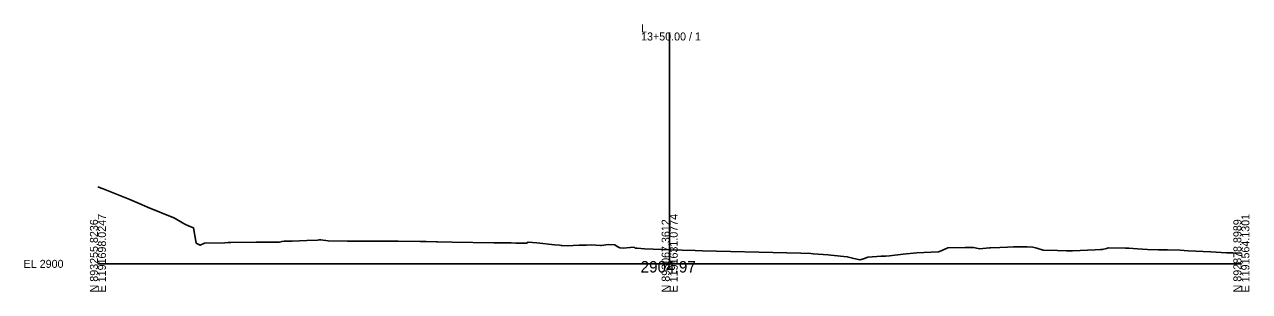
# Model space of a CAD drawing. Extents: x 1791751 to 1799722, y 648637 to 665635.
# Drawn here: x 1792163.2 to 1792591.7, y 656030.3 to 656123.9 of the extents above; entities that cross this region are included whole.
import ezdxf

# ---------------------------------------------------------------- set-up
doc = ezdxf.new("R2010")
doc.units = 0
for name, color, linetype in [('Exist Cross Section Cell', 7, 'Continuous'), ('Exist XS Center Line Elevation Label', 7, 'Continuous'), ('Exist XS Ground Line', 7, 'Continuous')]:
    doc.layers.add(name, color=color, linetype=linetype)

msp = doc.modelspace()

# ---------------------------------------------------------------- linework, layer by layer
at = {"layer": 'Exist Cross Section Cell'}
for p, q in [((1792388.88, 656040.04), (1792388.88, 656121.06)), ((1792388.88, 656040.04), (1792388.88, 656121.06)), ((1792388.88, 656040.04), (1792388.88, 656121.06)), ((1792188.88, 656040.04), (1792388.88, 656040.04)), ((1792188.88, 656040.04), (1792388.88, 656040.04)), ((1792188.88, 656040.04), (1792388.88, 656040.04)), ((1792388.88, 656040.04), (1792588.88, 656040.04)), ((1792388.88, 656040.04), (1792588.88, 656040.04)), ((1792388.88, 656040.04), (1792588.88, 656040.04))]:
    msp.add_line(p, q, dxfattribs=at)
at = {"layer": 'Exist XS Ground Line'}
msp.add_lwpolyline([(1792188.88, 656067.04), (1792190.34, 656066.46), (1792190.68, 656066.32), (1792200.03, 656062.58), (1792203.33, 656061.15), (1792204.12, 656060.81), (1792206.2, 656059.89), (1792215.41, 656056.14), (1792215.94, 656055.86), (1792218.48, 656054.42), (1792219.26, 656053.91), (1792220.83, 656053.24), (1792222.35, 656052.64), (1792223.27, 656047.32), (1792224.66, 656046.56), (1792226.12, 656047.31), (1792233.32, 656047.45), (1792234.41, 656047.47), (1792235.41, 656047.47), (1792244.2, 656047.65), (1792246.19, 656047.61), (1792248.65, 656047.68), (1792250.78, 656047.67), (1792252.35, 656047.67), (1792253.32, 656047.87), (1792254.01, 656047.94), (1792256.77, 656048.01), (1792261.95, 656048.25), (1792265.63, 656048.38), (1792266.25, 656048.39), (1792266.85, 656048.5), (1792269.43, 656048.15), (1792276.18, 656048.02), (1792279.82, 656047.94), (1792281.43, 656048), (1792281.93, 656047.99), (1792291.31, 656047.94), (1792293.88, 656047.93), (1792301.57, 656047.89), (1792302.86, 656047.89), (1792303.25, 656047.88), (1792303.65, 656047.88), (1792307.28, 656047.8), (1792307.67, 656047.79), (1792312.81, 656047.67), (1792327.42, 656047.44), (1792330.53, 656047.4), (1792333.48, 656047.35), (1792335.06, 656047.32), (1792338.82, 656047.26), (1792339.39, 656047.67), (1792342.38, 656047.35), (1792348.58, 656046.69), (1792350.31, 656046.52), (1792350.88, 656046.47), (1792351.19, 656046.44), (1792352.99, 656046.3), (1792357.22, 656046.58), (1792357.64, 656046.53), (1792359.83, 656046.6), (1792361.41, 656046.66), (1792364.7, 656046.47), (1792365.02, 656046.43), (1792367.41, 656046.78), (1792369.69, 656046.72), (1792370.54, 656046.06), (1792371.49, 656045.64), (1792372.57, 656045.57), (1792375.1, 656045.77), (1792376.42, 656045.83), (1792376.87, 656045.55), (1792377.56, 656045.51), (1792380.02, 656045.35), (1792383.16, 656045.22), (1792388.88, 656045), (1792389.22, 656044.99), (1792393.23, 656044.86), (1792397.79, 656044.69), (1792400.4, 656044.65), (1792429.91, 656043.86), (1792434.71, 656043.73), (1792438.27, 656043.64), (1792439.05, 656043.57), (1792444.35, 656043.19), (1792445.31, 656043.1), (1792451.02, 656042.52), (1792452.81, 656041.97), (1792455.46, 656041.49), (1792456.69, 656041.8), (1792458.22, 656042.41), (1792462.9, 656042.68), (1792464.33, 656042.75), (1792465.74, 656042.83), (1792470.6, 656043.47), (1792475.32, 656043.86), (1792477.76, 656043.97), (1792482.98, 656044.19), (1792483.91, 656044.6), (1792486.14, 656045.68), (1792492.25, 656045.71), (1792495.21, 656045.72), (1792496.85, 656045.41), (1792497.22, 656045.33), (1792500.82, 656045.62), (1792501.14, 656045.64), (1792504.37, 656045.76), (1792507.04, 656045.87), (1792509.2, 656045.96), (1792513.96, 656045.97), (1792515.9, 656045.93), (1792517.35, 656045.55), (1792519.49, 656044.83), (1792524.56, 656044.69), (1792527.75, 656044.6), (1792528.56, 656044.6), (1792529.81, 656044.61), (1792537.71, 656044.95), (1792539.6, 656045.02), (1792540.22, 656045.05), (1792541.75, 656045.37), (1792542.44, 656045.63), (1792548.32, 656045.54), (1792548.69, 656045.53), (1792549.46, 656045.49), (1792552.49, 656045.29), (1792555.99, 656045.01), (1792559.85, 656044.89), (1792563.05, 656044.89), (1792567.41, 656044.78), (1792570.32, 656044.62), (1792578.24, 656044.21), (1792583.62, 656043.95), (1792585.84, 656043.88), (1792588.88, 656043.78)], dxfattribs=at)
msp.add_lwpolyline([(1792188.88, 656067.04), (1792190.34, 656066.46), (1792190.68, 656066.32), (1792200.03, 656062.58), (1792203.33, 656061.15), (1792204.12, 656060.81), (1792206.2, 656059.89), (1792215.41, 656056.14), (1792215.94, 656055.86), (1792218.48, 656054.42), (1792219.26, 656053.91), (1792220.83, 656053.24), (1792222.35, 656052.64), (1792223.27, 656047.32), (1792224.66, 656046.56), (1792226.12, 656047.31), (1792233.32, 656047.45), (1792234.41, 656047.47), (1792235.41, 656047.47), (1792244.2, 656047.65), (1792246.19, 656047.61), (1792248.65, 656047.68), (1792250.78, 656047.67), (1792252.35, 656047.67), (1792253.32, 656047.87), (1792254.01, 656047.94), (1792256.77, 656048.01), (1792261.95, 656048.25), (1792265.63, 656048.38), (1792266.25, 656048.39), (1792266.85, 656048.5), (1792269.43, 656048.15), (1792276.18, 656048.02), (1792279.82, 656047.94), (1792281.43, 656048), (1792281.93, 656047.99), (1792291.31, 656047.94), (1792293.88, 656047.93), (1792301.57, 656047.89), (1792302.86, 656047.89), (1792303.25, 656047.88), (1792303.65, 656047.88), (1792307.28, 656047.8), (1792307.67, 656047.79), (1792312.81, 656047.67), (1792327.42, 656047.44), (1792330.53, 656047.4), (1792333.48, 656047.35), (1792335.06, 656047.32), (1792338.82, 656047.26), (1792339.39, 656047.67), (1792342.38, 656047.35), (1792348.58, 656046.69), (1792350.31, 656046.52), (1792350.88, 656046.47), (1792351.19, 656046.44), (1792352.99, 656046.3), (1792357.22, 656046.58), (1792357.64, 656046.53), (1792359.83, 656046.6), (1792361.41, 656046.66), (1792364.7, 656046.47), (1792365.02, 656046.43), (1792367.41, 656046.78), (1792369.69, 656046.72), (1792370.54, 656046.06), (1792371.49, 656045.64), (1792372.57, 656045.57), (1792375.1, 656045.77), (1792376.42, 656045.83), (1792376.87, 656045.55), (1792377.56, 656045.51), (1792380.02, 656045.35), (1792383.16, 656045.22), (1792388.88, 656045), (1792389.22, 656044.99), (1792393.23, 656044.86), (1792397.79, 656044.69), (1792400.4, 656044.65), (1792429.91, 656043.86), (1792434.71, 656043.73), (1792438.27, 656043.64), (1792439.05, 656043.57), (1792444.35, 656043.19), (1792445.31, 656043.1), (1792451.02, 656042.52), (1792452.81, 656041.97), (1792455.46, 656041.49), (1792456.69, 656041.8), (1792458.22, 656042.41), (1792462.9, 656042.68), (1792464.33, 656042.75), (1792465.74, 656042.83), (1792470.6, 656043.47), (1792475.32, 656043.86), (1792477.76, 656043.97), (1792482.98, 656044.19), (1792483.91, 656044.6), (1792486.14, 656045.68), (1792492.25, 656045.71), (1792495.21, 656045.72), (1792496.85, 656045.41), (1792497.22, 656045.33), (1792500.82, 656045.62), (1792501.14, 656045.64), (1792504.37, 656045.76), (1792507.04, 656045.87), (1792509.2, 656045.96), (1792513.96, 656045.97), (1792515.9, 656045.93), (1792517.35, 656045.55), (1792519.49, 656044.83), (1792524.56, 656044.69), (1792527.75, 656044.6), (1792528.56, 656044.6), (1792529.81, 656044.61), (1792537.71, 656044.95), (1792539.6, 656045.02), (1792540.22, 656045.05), (1792541.75, 656045.37), (1792542.44, 656045.63), (1792548.32, 656045.54), (1792548.69, 656045.53), (1792549.46, 656045.49), (1792552.49, 656045.29), (1792555.99, 656045.01), (1792559.85, 656044.89), (1792563.05, 656044.89), (1792567.41, 656044.78), (1792570.32, 656044.62), (1792578.24, 656044.21), (1792583.62, 656043.95), (1792585.84, 656043.88), (1792588.88, 656043.78)], dxfattribs=at)
msp.add_lwpolyline([(1792188.88, 656067.04), (1792190.34, 656066.46), (1792190.68, 656066.32), (1792200.03, 656062.58), (1792203.33, 656061.15), (1792204.12, 656060.81), (1792206.2, 656059.89), (1792215.41, 656056.14), (1792215.94, 656055.86), (1792218.48, 656054.42), (1792219.26, 656053.91), (1792220.83, 656053.24), (1792222.35, 656052.64), (1792223.27, 656047.32), (1792224.66, 656046.56), (1792226.12, 656047.31), (1792233.32, 656047.45), (1792234.41, 656047.47), (1792235.41, 656047.47), (1792244.2, 656047.65), (1792246.19, 656047.61), (1792248.65, 656047.68), (1792250.78, 656047.67), (1792252.35, 656047.67), (1792253.32, 656047.87), (1792254.01, 656047.94), (1792256.77, 656048.01), (1792261.95, 656048.25), (1792265.63, 656048.38), (1792266.25, 656048.39), (1792266.85, 656048.5), (1792269.43, 656048.15), (1792276.18, 656048.02), (1792279.82, 656047.94), (1792281.43, 656048), (1792281.93, 656047.99), (1792291.31, 656047.94), (1792293.88, 656047.93), (1792301.57, 656047.89), (1792302.86, 656047.89), (1792303.25, 656047.88), (1792303.65, 656047.88), (1792307.28, 656047.8), (1792307.67, 656047.79), (1792312.81, 656047.67), (1792327.42, 656047.44), (1792330.53, 656047.4), (1792333.48, 656047.35), (1792335.06, 656047.32), (1792338.82, 656047.26), (1792339.39, 656047.67), (1792342.38, 656047.35), (1792348.58, 656046.69), (1792350.31, 656046.52), (1792350.88, 656046.47), (1792351.19, 656046.44), (1792352.99, 656046.3), (1792357.22, 656046.58), (1792357.64, 656046.53), (1792359.83, 656046.6), (1792361.41, 656046.66), (1792364.7, 656046.47), (1792365.02, 656046.43), (1792367.41, 656046.78), (1792369.69, 656046.72), (1792370.54, 656046.06), (1792371.49, 656045.64), (1792372.57, 656045.57), (1792375.1, 656045.77), (1792376.42, 656045.83), (1792376.87, 656045.55), (1792377.56, 656045.51), (1792380.02, 656045.35), (1792383.16, 656045.22), (1792388.88, 656045), (1792389.22, 656044.99), (1792393.23, 656044.86), (1792397.79, 656044.69), (1792400.4, 656044.65), (1792429.91, 656043.86), (1792434.71, 656043.73), (1792438.27, 656043.64), (1792439.05, 656043.57), (1792444.35, 656043.19), (1792445.31, 656043.1), (1792451.02, 656042.52), (1792452.81, 656041.97), (1792455.46, 656041.49), (1792456.69, 656041.8), (1792458.22, 656042.41), (1792462.9, 656042.68), (1792464.33, 656042.75), (1792465.74, 656042.83), (1792470.6, 656043.47), (1792475.32, 656043.86), (1792477.76, 656043.97), (1792482.98, 656044.19), (1792483.91, 656044.6), (1792486.14, 656045.68), (1792492.25, 656045.71), (1792495.21, 656045.72), (1792496.85, 656045.41), (1792497.22, 656045.33), (1792500.82, 656045.62), (1792501.14, 656045.64), (1792504.37, 656045.76), (1792507.04, 656045.87), (1792509.2, 656045.96), (1792513.96, 656045.97), (1792515.9, 656045.93), (1792517.35, 656045.55), (1792519.49, 656044.83), (1792524.56, 656044.69), (1792527.75, 656044.6), (1792528.56, 656044.6), (1792529.81, 656044.61), (1792537.71, 656044.95), (1792539.6, 656045.02), (1792540.22, 656045.05), (1792541.75, 656045.37), (1792542.44, 656045.63), (1792548.32, 656045.54), (1792548.69, 656045.53), (1792549.46, 656045.49), (1792552.49, 656045.29), (1792555.99, 656045.01), (1792559.85, 656044.89), (1792563.05, 656044.89), (1792567.41, 656044.78), (1792570.32, 656044.62), (1792578.24, 656044.21), (1792583.62, 656043.95), (1792585.84, 656043.88), (1792588.88, 656043.78)], dxfattribs=at)
msp.add_lwpolyline([(1792188.88, 656067.04), (1792190.34, 656066.46), (1792190.68, 656066.32), (1792200.03, 656062.58), (1792203.33, 656061.15), (1792204.12, 656060.81), (1792206.2, 656059.89), (1792215.41, 656056.14), (1792215.94, 656055.86), (1792218.48, 656054.42), (1792219.26, 656053.91), (1792220.83, 656053.24), (1792222.35, 656052.64), (1792223.27, 656047.32), (1792224.66, 656046.56), (1792226.12, 656047.31), (1792233.32, 656047.45), (1792234.41, 656047.47), (1792235.41, 656047.47), (1792244.2, 656047.65), (1792246.19, 656047.61), (1792248.65, 656047.68), (1792250.78, 656047.67), (1792252.35, 656047.67), (1792253.32, 656047.87), (1792254.01, 656047.94), (1792256.77, 656048.01), (1792261.95, 656048.25), (1792265.63, 656048.38), (1792266.25, 656048.39), (1792266.85, 656048.5), (1792269.43, 656048.15), (1792276.18, 656048.02), (1792279.82, 656047.94), (1792281.43, 656048), (1792281.93, 656047.99), (1792291.31, 656047.94), (1792293.88, 656047.93), (1792301.57, 656047.89), (1792302.86, 656047.89), (1792303.25, 656047.88), (1792303.65, 656047.88), (1792307.28, 656047.8), (1792307.67, 656047.79), (1792312.81, 656047.67), (1792327.42, 656047.44), (1792330.53, 656047.4), (1792333.48, 656047.35), (1792335.06, 656047.32), (1792338.82, 656047.26), (1792339.39, 656047.67), (1792342.38, 656047.35), (1792348.58, 656046.69), (1792350.31, 656046.52), (1792350.88, 656046.47), (1792351.19, 656046.44), (1792352.99, 656046.3), (1792357.22, 656046.58), (1792357.64, 656046.53), (1792359.83, 656046.6), (1792361.41, 656046.66), (1792364.7, 656046.47), (1792365.02, 656046.43), (1792367.41, 656046.78), (1792369.69, 656046.72), (1792370.54, 656046.06), (1792371.49, 656045.64), (1792372.57, 656045.57), (1792375.1, 656045.77), (1792376.42, 656045.83), (1792376.87, 656045.55), (1792377.56, 656045.51), (1792380.02, 656045.35), (1792383.16, 656045.22), (1792388.88, 656045), (1792389.22, 656044.99), (1792393.23, 656044.86), (1792397.79, 656044.69), (1792400.4, 656044.65), (1792429.91, 656043.86), (1792434.71, 656043.73), (1792438.27, 656043.64), (1792439.05, 656043.57), (1792444.35, 656043.19), (1792445.31, 656043.1), (1792451.02, 656042.52), (1792452.81, 656041.97), (1792455.46, 656041.49), (1792456.69, 656041.8), (1792458.22, 656042.41), (1792462.9, 656042.68), (1792464.33, 656042.75), (1792465.74, 656042.83), (1792470.6, 656043.47), (1792475.32, 656043.86), (1792477.76, 656043.97), (1792482.98, 656044.19), (1792483.91, 656044.6), (1792486.14, 656045.68), (1792492.25, 656045.71), (1792495.21, 656045.72), (1792496.85, 656045.41), (1792497.22, 656045.33), (1792500.82, 656045.62), (1792501.14, 656045.64), (1792504.37, 656045.76), (1792507.04, 656045.87), (1792509.2, 656045.96), (1792513.96, 656045.97), (1792515.9, 656045.93), (1792517.35, 656045.55), (1792519.49, 656044.83), (1792524.56, 656044.69), (1792527.75, 656044.6), (1792528.56, 656044.6), (1792529.81, 656044.61), (1792537.71, 656044.95), (1792539.6, 656045.02), (1792540.22, 656045.05), (1792541.75, 656045.37), (1792542.44, 656045.63), (1792548.32, 656045.54), (1792548.69, 656045.53), (1792549.46, 656045.49), (1792552.49, 656045.29), (1792555.99, 656045.01), (1792559.85, 656044.89), (1792563.05, 656044.89), (1792567.41, 656044.78), (1792570.32, 656044.62), (1792578.24, 656044.21), (1792583.62, 656043.95), (1792585.84, 656043.88), (1792588.88, 656043.78)], dxfattribs=at)
msp.add_lwpolyline([(1792188.88, 656067.04), (1792190.34, 656066.46), (1792190.68, 656066.32), (1792200.03, 656062.58), (1792203.33, 656061.15), (1792204.12, 656060.81), (1792206.2, 656059.89), (1792215.41, 656056.14), (1792215.94, 656055.86), (1792218.48, 656054.42), (1792219.26, 656053.91), (1792220.83, 656053.24), (1792222.35, 656052.64), (1792223.27, 656047.32), (1792224.66, 656046.56), (1792226.12, 656047.31), (1792233.32, 656047.45), (1792234.41, 656047.47), (1792235.41, 656047.47), (1792244.2, 656047.65), (1792246.19, 656047.61), (1792248.65, 656047.68), (1792250.78, 656047.67), (1792252.35, 656047.67), (1792253.32, 656047.87), (1792254.01, 656047.94), (1792256.77, 656048.01), (1792261.95, 656048.25), (1792265.63, 656048.38), (1792266.25, 656048.39), (1792266.85, 656048.5), (1792269.43, 656048.15), (1792276.18, 656048.02), (1792279.82, 656047.94), (1792281.43, 656048), (1792281.93, 656047.99), (1792291.31, 656047.94), (1792293.88, 656047.93), (1792301.57, 656047.89), (1792302.86, 656047.89), (1792303.25, 656047.88), (1792303.65, 656047.88), (1792307.28, 656047.8), (1792307.67, 656047.79), (1792312.81, 656047.67), (1792327.42, 656047.44), (1792330.53, 656047.4), (1792333.48, 656047.35), (1792335.06, 656047.32), (1792338.82, 656047.26), (1792339.39, 656047.67), (1792342.38, 656047.35), (1792348.58, 656046.69), (1792350.31, 656046.52), (1792350.88, 656046.47), (1792351.19, 656046.44), (1792352.99, 656046.3), (1792357.22, 656046.58), (1792357.64, 656046.53), (1792359.83, 656046.6), (1792361.41, 656046.66), (1792364.7, 656046.47), (1792365.02, 656046.43), (1792367.41, 656046.78), (1792369.69, 656046.72), (1792370.54, 656046.06), (1792371.49, 656045.64), (1792372.57, 656045.57), (1792375.1, 656045.77), (1792376.42, 656045.83), (1792376.87, 656045.55), (1792377.56, 656045.51), (1792380.02, 656045.35), (1792383.16, 656045.22), (1792388.88, 656045), (1792389.22, 656044.99), (1792393.23, 656044.86), (1792397.79, 656044.69), (1792400.4, 656044.65), (1792429.91, 656043.86), (1792434.71, 656043.73), (1792438.27, 656043.64), (1792439.05, 656043.57), (1792444.35, 656043.19), (1792445.31, 656043.1), (1792451.02, 656042.52), (1792452.81, 656041.97), (1792455.46, 656041.49), (1792456.69, 656041.8), (1792458.22, 656042.41), (1792462.9, 656042.68), (1792464.33, 656042.75), (1792465.74, 656042.83), (1792470.6, 656043.47), (1792475.32, 656043.86), (1792477.76, 656043.97), (1792482.98, 656044.19), (1792483.91, 656044.6), (1792486.14, 656045.68), (1792492.25, 656045.71), (1792495.21, 656045.72), (1792496.85, 656045.41), (1792497.22, 656045.33), (1792500.82, 656045.62), (1792501.14, 656045.64), (1792504.37, 656045.76), (1792507.04, 656045.87), (1792509.2, 656045.96), (1792513.96, 656045.97), (1792515.9, 656045.93), (1792517.35, 656045.55), (1792519.49, 656044.83), (1792524.56, 656044.69), (1792527.75, 656044.6), (1792528.56, 656044.6), (1792529.81, 656044.61), (1792537.71, 656044.95), (1792539.6, 656045.02), (1792540.22, 656045.05), (1792541.75, 656045.37), (1792542.44, 656045.63), (1792548.32, 656045.54), (1792548.69, 656045.53), (1792549.46, 656045.49), (1792552.49, 656045.29), (1792555.99, 656045.01), (1792559.85, 656044.89), (1792563.05, 656044.89), (1792567.41, 656044.78), (1792570.32, 656044.62), (1792578.24, 656044.21), (1792583.62, 656043.95), (1792585.84, 656043.88), (1792588.88, 656043.78)], dxfattribs=at)

# ---------------------------------------------------------------- texts
at = {"layer": 'Exist Cross Section Cell'}
for s, p in [('L', (1792378.88, 656121.06)), ('L', (1792378.88, 656121.06)), ('L', (1792378.88, 656121.06)), ('13+50.00 / 1', (1792378.88, 656118.26)), ('13+50.00 / 1', (1792378.88, 656118.26)), ('13+50.00 / 1', (1792378.88, 656118.26)), ('EL 2900', (1792162.88, 656038.64)), ('EL 2900', (1792162.88, 656038.64)), ('EL 2900', (1792162.88, 656038.64))]:
    msp.add_text(s, height=2.8, dxfattribs=at).set_placement(p)
for s, p in [('N 893255.8236', (1792188.88, 656030.04)), ('N 893255.8236', (1792188.88, 656030.04)), ('N 893255.8236', (1792188.88, 656030.04)), ('E 1191698.0247', (1792191.68, 656030.04)), ('E 1191698.0247', (1792191.68, 656030.04)), ('E 1191698.0247', (1792191.68, 656030.04)), ('N 893067.3612', (1792388.88, 656030.04)), ('N 893067.3612', (1792388.88, 656030.04)), ('N 893067.3612', (1792388.88, 656030.04)), ('E 1191631.0774', (1792391.68, 656030.04)), ('E 1191631.0774', (1792391.68, 656030.04)), ('E 1191631.0774', (1792391.68, 656030.04)), ('N 892878.8989', (1792588.88, 656030.04)), ('N 892878.8989', (1792588.88, 656030.04)), ('N 892878.8989', (1792588.88, 656030.04)), ('E 1191564.1301', (1792591.68, 656030.04)), ('E 1191564.1301', (1792591.68, 656030.04)), ('E 1191564.1301', (1792591.68, 656030.04))]:
    msp.add_text(s, height=2.8, rotation=90, dxfattribs=at).set_placement(p)
at = {"layer": 'Exist XS Center Line Elevation Label'}
for height, p in [(4, (1792378.7, 656037)), (4, (1792378.7, 656037)), (1, (1792386.48, 656040))]:
    msp.add_text('2904.97', height=height, dxfattribs=at).set_placement(p)

doc.saveas('drawing.dxf')
